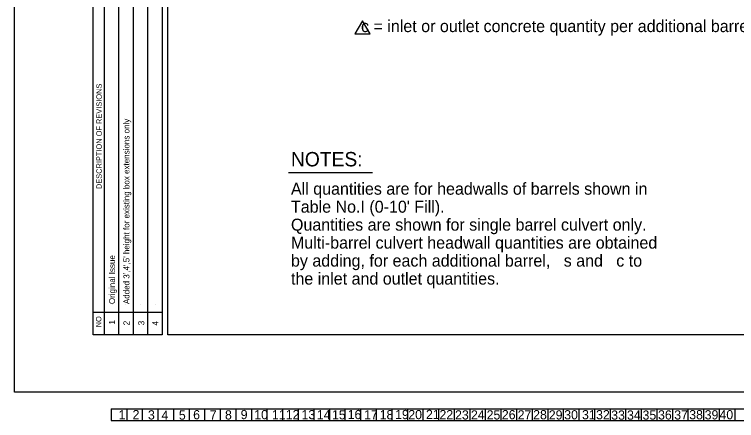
# Model space of a CAD drawing. Extents: x -0.08 to 2.83, y -0.03 to 1.92.
# Drawn here: x 0 to 0.784, y -0.031 to 0.411 of the extents above; entities that cross this region are included whole.
import ezdxf

# ---------------------------------------------------------------- set-up
doc = ezdxf.new("R2010")
doc.units = 0
for name, color, linetype in [('1', 7, 'Continuous'), ('10', 7, 'Continuous'), ('11', 7, 'Continuous'), ('12', 7, 'Continuous'), ('13', 7, 'Continuous'), ('14', 7, 'Continuous'), ('15', 7, 'Continuous'), ('16', 7, 'Continuous'), ('17', 7, 'Continuous'), ('18', 7, 'Continuous'), ('19', 7, 'Continuous'), ('2', 7, 'Continuous'), ('20', 7, 'Continuous'), ('21', 7, 'Continuous'), ('22', 7, 'Continuous'), ('23', 7, 'Continuous'), ('24', 7, 'Continuous'), ('25', 7, 'Continuous'), ('26', 7, 'Continuous'), ('27', 7, 'Continuous'), ('28', 7, 'Continuous'), ('29', 7, 'Continuous'), ('3', 7, 'Continuous'), ('30', 7, 'Continuous'), ('31', 7, 'Continuous'), ('32', 7, 'Continuous'), ('33', 7, 'Continuous'), ('34', 7, 'Continuous'), ('35', 7, 'Continuous'), ('36', 7, 'Continuous'), ('37', 7, 'Continuous'), ('38', 7, 'Continuous'), ('39', 7, 'Continuous'), ('4', 7, 'Continuous'), ('40', 7, 'Continuous'), ('5', 7, 'Continuous'), ('57', 7, 'Continuous'), ('6', 7, 'Continuous'), ('62', 7, 'Continuous'), ('63', 7, 'Continuous'), ('7', 7, 'Continuous'), ('8', 7, 'Continuous'), ('9', 7, 'Continuous')]:
    doc.layers.add(name, color=color, linetype=linetype)

msp = doc.modelspace()

# ---------------------------------------------------------------- linework, layer by layer
at = {"layer": '57'}
for p, q in [((0.37799, 0.40352), (0.36978, 0.3893)), ((0.38619, 0.3893), (0.37799, 0.40352)), ((0.36978, 0.3893), (0.38619, 0.3893)), ((0.29774, 0.23871), (0.38872, 0.23871))]:
    msp.add_line(p, q, dxfattribs=at)
at = {"layer": '62'}
for p, q in [((0.10603, 0.09579), (0.10603, 0.09579)), ((0.121, 0.09544), (0.121, 0.09544)), ((0.13668, 0.09544), (0.13668, 0.09544)), ((0.15304, 0.09579), (0.15304, 0.09579)), ((0.10494, -0.01804), (1.17174, -0.01804)), ((0.10494, -0.01804), (0.10494, -0.03074)), ((0.12188, -0.01804), (0.12188, -0.03074)), ((0.13881, -0.01804), (0.13881, -0.03074)), ((0.15574, -0.01804), (0.15574, -0.03074)), ((0.17267, -0.01804), (0.17267, -0.03074)), ((0.18961, -0.01804), (0.18961, -0.03074)), ((0.20654, -0.01804), (0.20654, -0.03074)), ((0.22348, -0.01804), (0.22348, -0.03074)), ((0.24041, -0.01804), (0.24041, -0.03074)), ((0.25734, -0.01804), (0.25734, -0.03074)), ((0.27427, -0.01804), (0.27427, -0.03074)), ((0.29121, -0.01804), (0.29121, -0.03074)), ((0.30814, -0.01804), (0.30814, -0.03074)), ((0.32508, -0.01804), (0.32508, -0.03074)), ((0.34201, -0.01804), (0.34201, -0.03074)), ((0.35894, -0.01804), (0.35894, -0.03074)), ((0.37588, -0.01804), (0.37588, -0.03074)), ((0.39281, -0.01804), (0.39281, -0.03074)), ((0.40974, -0.01804), (0.40974, -0.03074)), ((0.42668, -0.01804), (0.42668, -0.03074)), ((0.44361, -0.01804), (0.44361, -0.03074)), ((0.46054, -0.01804), (0.46054, -0.03074)), ((0.47748, -0.01804), (0.47748, -0.03074)), ((0.49441, -0.01804), (0.49441, -0.03074)), ((0.51134, -0.01804), (0.51134, -0.03074)), ((0.52828, -0.01804), (0.52828, -0.03074)), ((0.54521, -0.01804), (0.54521, -0.03074)), ((0.56214, -0.01804), (0.56214, -0.03074)), ((0.57908, -0.01804), (0.57908, -0.03074)), ((0.59601, -0.01804), (0.59601, -0.03074)), ((0.61294, -0.01804), (0.61294, -0.03074)), ((0.62988, -0.01804), (0.62988, -0.03074)), ((0.64681, -0.01804), (0.64681, -0.03074)), ((0.66374, -0.01804), (0.66374, -0.03074)), ((0.68068, -0.01804), (0.68068, -0.03074)), ((0.69761, -0.01804), (0.69761, -0.03074)), ((0.71454, -0.01804), (0.71454, -0.03074)), ((0.73147, -0.01804), (0.73147, -0.03074)), ((0.74841, -0.01804), (0.74841, -0.03074)), ((0.76534, -0.01804), (0.76534, -0.03074)), ((0.78228, -0.01804), (0.78228, -0.03074)), ((0.10494, -0.03074), (1.17174, -0.03074))]:
    msp.add_line(p, q, dxfattribs=at)
at = {"layer": '63'}
for p, q in [((0, 0), (0, 1.83333)), ((0.08543, 0.06244), (0.08543, 0.56244)), ((0.09792, 0.06244), (0.09792, 0.56244)), ((0.11353, 0.06259), (0.11353, 0.56244)), ((0.12914, 0.06275), (0.12914, 0.56244)), ((0.14474, 0.0629), (0.14474, 0.56244)), ((0.16043, 0.56244), (0.16043, 0.06244)), ((0.08543, 0.08707), (0.16043, 0.08707)), ((0.16043, 0.06244), (0.08543, 0.06244)), ((2.83333, 0), (0, 0))]:
    msp.add_line(p, q, dxfattribs=at)
msp.add_lwpolyline([(0.16668, 0.06244), (0.16668, 1.77077), (2.72918, 1.77077), (2.72918, 0.10411), (2.56251, 0.10411), (2.56251, 0.14578), (2.07387, 0.14578), (2.07387, 0.06244)], close=True, dxfattribs=at)

# ---------------------------------------------------------------- texts
at = {"layer": '1'}
msp.add_text('1', height=0.01, rotation=360, dxfattribs=at).set_placement((0.11316, -0.02944))
at = {"layer": '10'}
msp.add_text('10', height=0.01, rotation=360, dxfattribs=at).set_placement((0.26046, -0.02928))
at = {"layer": '11'}
msp.add_text('11', height=0.01, rotation=360, dxfattribs=at).set_placement((0.2796, -0.02937))
at = {"layer": '12'}
msp.add_text('12', height=0.01, rotation=360, dxfattribs=at).set_placement((0.29469, -0.02925))
at = {"layer": '13'}
msp.add_text('13', height=0.01, rotation=360, dxfattribs=at).set_placement((0.31181, -0.02928))
at = {"layer": '14'}
msp.add_text('14', height=0.01, rotation=360, dxfattribs=at).set_placement((0.32844, -0.02939))
at = {"layer": '15'}
msp.add_text('15', height=0.01, rotation=360, dxfattribs=at).set_placement((0.34488, -0.02946))
at = {"layer": '16'}
msp.add_text('16', height=0.01, rotation=360, dxfattribs=at).set_placement((0.3619, -0.02918))
at = {"layer": '17'}
msp.add_text('17', height=0.01, rotation=360, dxfattribs=at).set_placement((0.3797, -0.02946))
at = {"layer": '18'}
msp.add_text('18', height=0.01, rotation=360, dxfattribs=at).set_placement((0.39663, -0.02938))
at = {"layer": '19'}
msp.add_text('19', height=0.01, rotation=360, dxfattribs=at).set_placement((0.4134, -0.02918))
at = {"layer": '2'}
msp.add_text('2', height=0.01, rotation=360, dxfattribs=at).set_placement((0.12828, -0.02928))
at = {"layer": '20'}
msp.add_text('20', height=0.01, rotation=360, dxfattribs=at).set_placement((0.42774, -0.02926))
at = {"layer": '21'}
msp.add_text('21', height=0.01, rotation=360, dxfattribs=at).set_placement((0.44688, -0.02909))
at = {"layer": '22'}
msp.add_text('22', height=0.01, rotation=360, dxfattribs=at).set_placement((0.46158, -0.02929))
at = {"layer": '23'}
msp.add_text('23', height=0.01, rotation=360, dxfattribs=at).set_placement((0.47852, -0.02958))
at = {"layer": '24'}
msp.add_text('24', height=0.01, rotation=360, dxfattribs=at).set_placement((0.49576, -0.02958))
at = {"layer": '25'}
msp.add_text('25', height=0.01, rotation=360, dxfattribs=at).set_placement((0.51281, -0.02958))
at = {"layer": '26'}
msp.add_text('26', height=0.01, rotation=360, dxfattribs=at).set_placement((0.52931, -0.02936))
at = {"layer": '27'}
msp.add_text('27', height=0.01, rotation=360, dxfattribs=at).set_placement((0.54648, -0.02958))
at = {"layer": '28'}
msp.add_text('28', height=0.01, rotation=360, dxfattribs=at).set_placement((0.56333, -0.02938))
at = {"layer": '29'}
msp.add_text('29', height=0.01, rotation=360, dxfattribs=at).set_placement((0.58032, -0.02956))
at = {"layer": '3'}
msp.add_text('3', height=0.01, rotation=360, dxfattribs=at).set_placement((0.145, -0.02955))
at = {"layer": '30'}
msp.add_text('30', height=0.01, rotation=360, dxfattribs=at).set_placement((0.59706, -0.02946))
at = {"layer": '31'}
msp.add_text('31', height=0.01, rotation=360, dxfattribs=at).set_placement((0.61636, -0.02938))
at = {"layer": '32'}
msp.add_text('32', height=0.01, rotation=360, dxfattribs=at).set_placement((0.63163, -0.02938))
at = {"layer": '33'}
msp.add_text('33', height=0.01, rotation=360, dxfattribs=at).set_placement((0.64808, -0.02978))
at = {"layer": '34'}
msp.add_text('34', height=0.01, rotation=360, dxfattribs=at).set_placement((0.66527, -0.02978))
at = {"layer": '35'}
msp.add_text('35', height=0.01, rotation=360, dxfattribs=at).set_placement((0.68209, -0.02978))
at = {"layer": '36'}
msp.add_text('36', height=0.01, rotation=360, dxfattribs=at).set_placement((0.69895, -0.02958))
at = {"layer": '37'}
msp.add_text('37', height=0.01, rotation=360, dxfattribs=at).set_placement((0.71654, -0.02958))
at = {"layer": '38'}
msp.add_text('38', height=0.01, rotation=360, dxfattribs=at).set_placement((0.73281, -0.02938))
at = {"layer": '39'}
msp.add_text('39', height=0.01, rotation=360, dxfattribs=at).set_placement((0.74958, -0.0295))
at = {"layer": '4'}
msp.add_text('4', height=0.01, rotation=360, dxfattribs=at).set_placement((0.15973, -0.02984))
at = {"layer": '40'}
msp.add_text('40', height=0.01, rotation=360, dxfattribs=at).set_placement((0.76566, -0.02938))
at = {"layer": '5'}
msp.add_text('5', height=0.01, rotation=360, dxfattribs=at).set_placement((0.17858, -0.02977))
at = {"layer": '57'}
for s, height, p in [('  c = inlet or outlet concrete quantity per additional barrel.', 0.0130208, (0.36671, 0.39132)), ('NOTES:', 0.015625, (0.3003, 0.24542)), ('All quantities are for headwalls of barrels shown in', 0.0130208, (0.3003, 0.21465)), ("Table No.I (0-10' Fill).", 0.0130208, (0.3003, 0.19512)), ('Quantities are shown for single barrel culvert only.', 0.0130208, (0.3003, 0.17559)), ('Multi-barrel culvert headwall quantities are obtained', 0.0130208, (0.3003, 0.15606)), ('by adding, for each additional barrel,   s and   c to', 0.0130208, (0.3003, 0.13653)), ('the inlet and outlet quantities.', 0.0130208, (0.3003, 0.117))]:
    msp.add_text(s, height=height, dxfattribs=at).set_placement(p)
at = {"layer": '6'}
msp.add_text('6', height=0.01, rotation=360, dxfattribs=at).set_placement((0.19409, -0.02938))
at = {"layer": '62'}
for s, height, p in [("Added 3',4',5' height for existing box extensions only", 0.0065083, (0.12488, 0.09579)), ('Original Issue                                                   ', 0.0065084, (0.10928, 0.09579))]:
    msp.add_text(s, height=height, rotation=90, dxfattribs=at).set_placement(p)
at = {"layer": '63'}
for s, height, p in [('DESCRIPTION OF REVISIONS', 0.0058333, (0.09477, 0.22076)), ('NO', 0.005833, (0.09439, 0.07059)), ('1', 0.00667, (0.10936, 0.0735)), ('2', 0.00667, (0.12503, 0.07272)), ('3', 0.00667, (0.14105, 0.07272)), ('4', 0.00667, (0.15638, 0.07237))]:
    msp.add_text(s, height=height, rotation=90, dxfattribs=at).set_placement(p)
at = {"layer": '7'}
msp.add_text('7', height=0.01, rotation=360, dxfattribs=at).set_placement((0.21211, -0.02964))
at = {"layer": '8'}
msp.add_text('8', height=0.01, rotation=360, dxfattribs=at).set_placement((0.22865, -0.02958))
at = {"layer": '9'}
msp.add_text('9', height=0.01, rotation=360, dxfattribs=at).set_placement((0.24573, -0.02921))

doc.saveas('drawing.dxf')
